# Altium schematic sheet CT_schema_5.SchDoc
size 205 x 258 mm
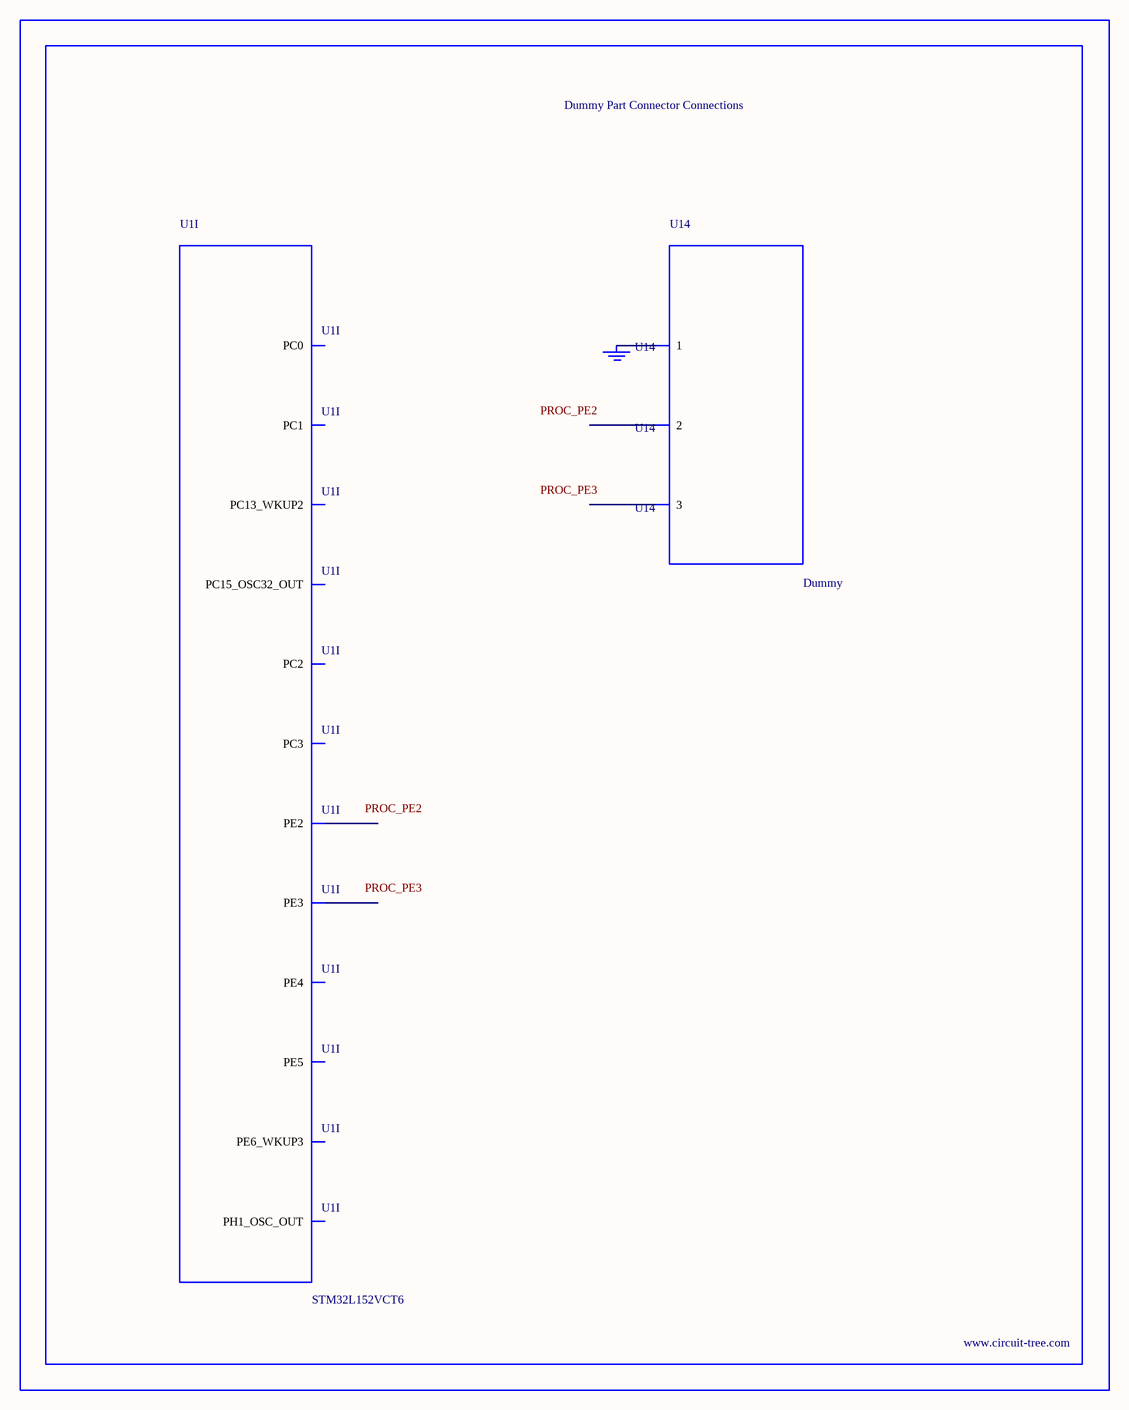
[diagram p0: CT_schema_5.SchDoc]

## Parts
BORDER4  (no value)
GND_INSTANCE_4_0  (no value)
U1  STM32L152VCT6  [LQFP100]  (part I of 9)
U14  Dummy  [DUMMY_PACKAGE_141]

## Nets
NetGND_INSTANCE_4_0_0: GND_INSTANCE_4_0.0(GND) U14.1

Not connected (* = marked no-connect by the designer): U1 1(PE2) 2(PE3) 3(PE4) 4(PE5) 5(PE6_WKUP3) 7(PC13_WKUP2) 9(PC15_OSC32_OUT) 13(PH1_OSC_OUT) 15(PC0) 16(PC1) 17(PC2) 18(PC3); U14 2 3

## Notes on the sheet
- Labels drawn without touching a wire or pin: PROC_PE2, PROC_PE3

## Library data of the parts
BORDER4 = BORDER_PAGE4
GND_INSTANCE_4_0 = GND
